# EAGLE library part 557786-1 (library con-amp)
AMP connector
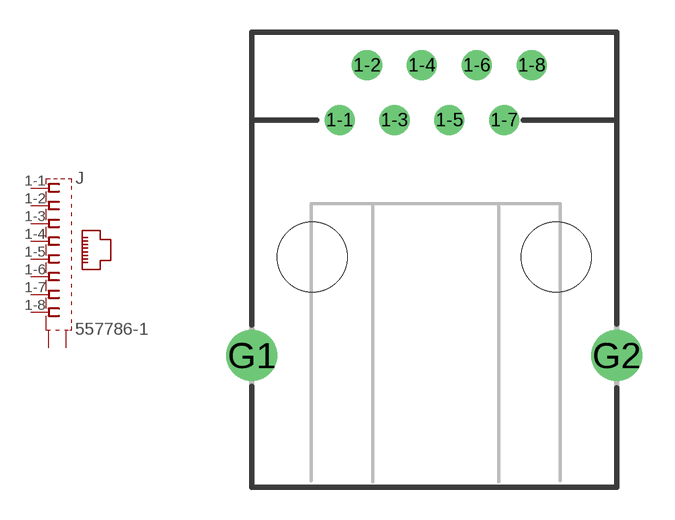
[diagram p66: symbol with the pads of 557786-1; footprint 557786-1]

Designator prefix J

## 557786-1 (MF: TYCO ELECTRONICS; MPN: 5557786-1; OC_FARNELL: 1777355; OC_NEWARK: 42K8769)  [557786-1]
1-1  1  pas
1-2  2  pas
1-3  3  pas
1-4  4  pas
1-5  5  pas
1-6  6  pas
1-7  7  pas
1-8  8  pas
G1  S2  pas
G2  S1  pas

## Footprint 557786-1 (pad centres in mm)
Modular Jack Shielded
drill 0.889 round: 1-1 -4.445,6.35; 1-2 -3.175,8.89; 1-3 -1.905,6.35; 1-4 -0.635,8.89; 1-5 0.635,6.35; 1-6 1.905,8.89; 1-7 3.175,6.35; 1-8 4.445,8.89
drill 1.575 pad 2.184 round: G1 -8.509,-4.572; G2 8.382,-4.572
hole 3.251 at -5.715,0
hole 3.251 at 5.588,0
